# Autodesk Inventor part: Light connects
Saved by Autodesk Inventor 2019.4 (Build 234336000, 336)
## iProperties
Created: 2019-12
Part Number: Light connects
Material: Generic
Document SubType Name: Modeling
Designer: Administrator
Density: 1 g/cm^3
Appearance: Default
Title: Light connects v4
Author: Administrator
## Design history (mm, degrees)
feature "Body1"
feature "Body2"
body "Solid1"
body "Solid2"
